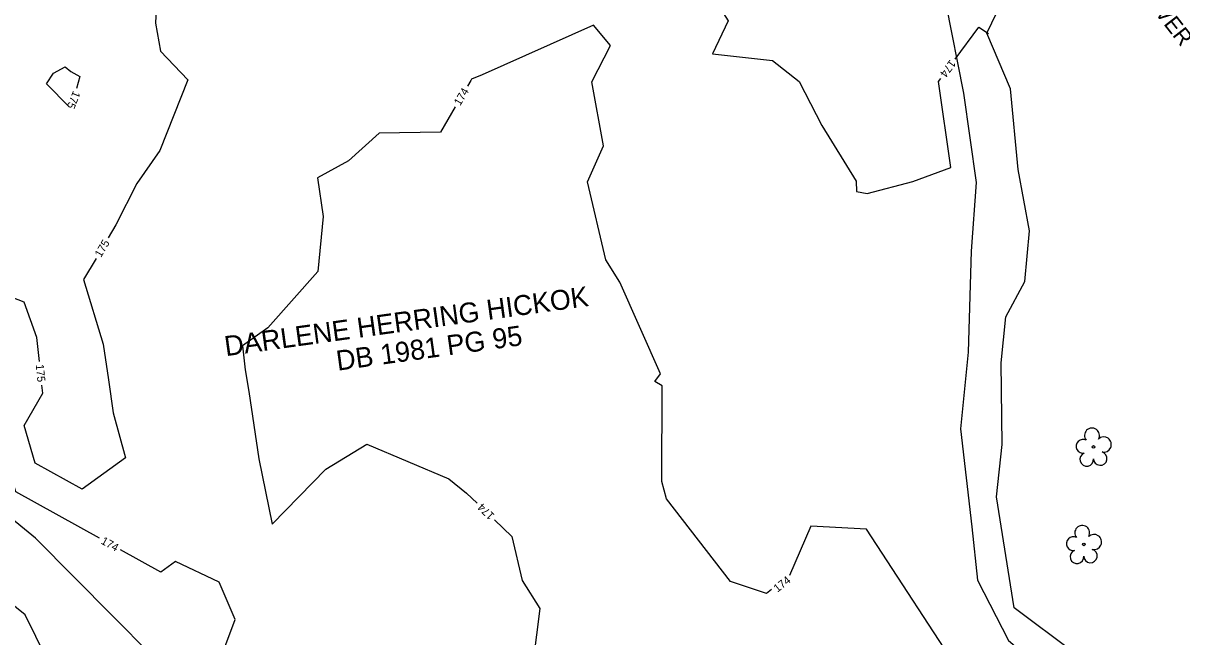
# Model space of a CAD drawing. Extents: x 2086416 to 2115205, y 575507 to 632762.
# Drawn here: x 2111776.5 to 2112066, y 581467.3 to 581620.8 of the extents above; entities that cross this region are included whole.
import ezdxf

# ---------------------------------------------------------------- set-up
doc = ezdxf.new("R2010")
doc.units = 0
for name, color, linetype in [('DTM Contours Major', 7, 'Continuous'), ('DTM Contours Major Text', 7, 'Continuous'), ('DTM Contours Minor', 7, 'Continuous'), ('DTM Contours Minor Text', 7, 'Continuous'), ('Exist Hydro Stream or Body of Water', 7, 'Continuous'), ('Exist Hydro Stream or Body of Water Text', 7, 'Continuous'), ('Exist Property Deed Book Text', 7, 'Continuous'), ('Exist Property Owner Text', 7, 'Continuous'), ('Exist Vegetation Tree CELL', 7, 'Continuous'), ('Exist Vegetation Woods Line', 7, 'Continuous')]:
    doc.layers.add(name, color=color, linetype=linetype)

# ---------------------------------------------------------------- blocks, each defined once
blk = doc.blocks.new('EXIST VEGETATION TREE')
at = {"layer": 'Exist Vegetation Tree CELL'}
blk.add_line((0, 0), (0, 0), dxfattribs=at)
blk.add_circle((0, 0), 0.00652, dxfattribs=at)
for centre, radius, start, end in [((-0.0077, 0.0575), 0.0371, 330.16508, 219.71335), ((-0.0521, 0.0031), 0.0345, 62.66361, 279.3457), ((0.051, 0.0118), 0.038, 257.1011, 134.19993), ((-0.0341, -0.0624), 0.0338, 111.56708, 6.23104), ((0.0335, -0.058), 0.034, 181.28216, 74.55999)]:
    blk.add_arc(centre, radius, start, end, dxfattribs=at)

msp = doc.modelspace()

# ---------------------------------------------------------------- linework, layer by layer
at = {"layer": 'DTM Contours Major'}
for points in [[(2111820.07, 581645.83), (2111817.92, 581646.44), (2111808.25, 581646.5), (2111811.2, 581641.49), (2111810.29, 581636.32), (2111809.51, 581620.82), (2111810.8, 581613.76), (2111817.65, 581606.62), (2111810.63, 581588.91), (2111804.83, 581580.65), (2111799.65, 581570.34), (2111797.73, 581567.1)], [(2111782.3, 581605.61), (2111784.01, 581608.29), (2111786.99, 581609.88), (2111788.36, 581608.71), (2111790.62, 581607.48), (2111789.82, 581604.42)], [(2111780.53, 581536.2), (2111779.91, 581542.21), (2111776.72, 581551.05), (2111767.61, 581554.53), (2111746.99, 581573.66), (2111745.59, 581575.02), (2111748.2, 581578.53), (2111769.31, 581602.49), (2111766.72, 581604.09), (2111762.55, 581607.47)], [(2111787.98, 581599.85), (2111782.3, 581605.61)], [(2111794.67, 581561.93), (2111791.54, 581556.65), (2111796.48, 581540.55), (2111797.78, 581531.62), (2111798.98, 581523.31), (2111802.05, 581512.09), (2111791.22, 581504.22), (2111779.44, 581510.73), (2111776.74, 581520.15), (2111781.34, 581528.23), (2111781.14, 581530.23)]]:
    msp.add_lwpolyline(points, dxfattribs=at)
at = {"layer": 'DTM Contours Minor'}
for points in [[(2112001.57, 581666.12), (2111965.52, 581661.61), (2111964.4, 581661.24), (2111963.9, 581661.19), (2111958.38, 581660.11), (2111945.74, 581643.25), (2111945.53, 581632.64), (2111952.64, 581621.35), (2111948.73, 581613.13), (2111963.74, 581611.46), (2111970.42, 581606.19), (2111976.09, 581595.16), (2111984.65, 581581.25), (2111984.7, 581578.65), (2111987.39, 581578.17), (2111998.82, 581581.21), (2112008.29, 581584.73), (2112005.23, 581606.22), (2112005.78, 581606.97)], [(2111963.5, 581479.12), (2111962.2, 581478.15), (2111953.21, 581481.17), (2111937.2, 581501.82), (2111936.07, 581506.16), (2111936.16, 581530.08), (2111934.34, 581531.17), (2111935.7, 581533.07), (2111925.59, 581555.99), (2111922.09, 581561.58), (2111917.53, 581581.13), (2111921.47, 581590.14), (2111918.62, 581606.14), (2111923.22, 581615.22), (2111918.98, 581620.26), (2111891.19, 581607.9), (2111888.52, 581606.78), (2111888.34, 581606.47), (2111887.5, 581605.04)], [(2112009.35, 581611.79), (2112015.27, 581619.77), (2112017.74, 581618.23)], [(2111884.45, 581599.87), (2111880.73, 581593.56), (2111865.45, 581593.25), (2111857.75, 581586.36), (2111850.01, 581582.13), (2111851.41, 581572.47), (2111850.12, 581558.71), (2111837.61, 581544.61), (2111831.26, 581540.08), (2111831.96, 581534.09), (2111832.86, 581528.7), (2111835.36, 581511.87), (2111838.72, 581495.5), (2111852.1, 581509.28), (2111862.32, 581515.47), (2111882.86, 581506.83), (2111887.27, 581503.23), (2111889.92, 581500.71)], [(2111795.57, 581491.95), (2111774.6, 581503.54), (2111772.79, 581509.85), (2111742.06, 581525.95)], [(2111894.26, 581496.57), (2111898.61, 581492.43), (2111901.19, 581481.43), (2111905.56, 581474.44), (2111901.59, 581442.83), (2111895.67, 581435.72), (2111904.81, 581432.38)], [(2111936.8, 581431.38), (2111937.22, 581432.68), (2111937.59, 581431.38), (2112017, 581428.25), (2112026.43, 581428.02), (2112017.76, 581430.28), (2112017.05, 581436.29), (2112012.18, 581454.89), (2112012.09, 581456.17), (2112011.8, 581456.57), (2111987.24, 581494.26), (2111973.35, 581495.02), (2111968.01, 581482.65)], [(2111808.47, 581449.49), (2111823.16, 581455.94), (2111824.76, 581459.12), (2111829.42, 581471.68), (2111825.46, 581480.96), (2111814.57, 581486.18), (2111810.87, 581483.49), (2111800.82, 581489.04)]]:
    msp.add_lwpolyline(points, dxfattribs=at)
at = {"layer": 'Exist Hydro Stream or Body of Water'}
for points in [[(2112026.79, 581556.19), (2112027.99, 581568.85), (2112025.16, 581584.18), (2112023.21, 581604.37), (2112017.27, 581618.27), (2112027.13, 581638.7)], [(2111785.01, 581456.38), (2111776.98, 581472.85), (2111753.02, 581492.1), (2111736.76, 581510.47), (2111717.38, 581521.12), (2111676.84, 581560.27), (2111646, 581586.7)], [(2112067.22, 581424.64), (2112074.1, 581427.73), (2112073.39, 581436.72), (2112064.5, 581445.16), (2112053.96, 581452.19), (2112024.09, 581474.58), (2112019.7, 581502.3), (2112021.09, 581515.42), (2112020.9, 581535.88), (2112022.05, 581547.38), (2112026.79, 581556.19)]]:
    msp.add_lwpolyline(points, dxfattribs=at)
at = {"layer": 'Exist Vegetation Woods Line'}
for points in [[(2112016.22, 581659.52), (2112010.15, 581640.89), (2112007.07, 581625.66), (2112011.47, 581603.31), (2112014.66, 581580.91), (2112013.34, 581563.73), (2112012.63, 581538.51), (2112010.71, 581519.35), (2112013.56, 581494.84), (2112014.97, 581481.49), (2112022.73, 581466.4), (2112037.51, 581453.75), (2112050.78, 581446.7), (2112062.82, 581439.28), (2112065.18, 581428.19)], [(2111779.57, 581491.97), (2111763.79, 581504.85), (2111745.34, 581525.06), (2111717.3, 581555.59), (2111690.35, 581575.95), (2111665.09, 581587.14), (2111644.35, 581594.34), (2111622.46, 581605.4), (2111614.18, 581617.92), (2111615.41, 581630.25), (2111644.69, 581636.02), (2111711.67, 581643.9), (2111763.23, 581655.57), (2111785.51, 581656)], [(2111823.9, 581373.12), (2111830.89, 581408.91), (2111827.79, 581443.34), (2111779.57, 581491.97)]]:
    msp.add_lwpolyline(points, dxfattribs=at)

# ---------------------------------------------------------------- block references
at = {"layer": 'Exist Vegetation Tree CELL', "xscale": 50, "yscale": 50}
for p in [(2112043.96, 581514.81), (2112041.52, 581490.44)]:
    msp.add_blockref('EXIST VEGETATION TREE', p, dxfattribs=at)

# ---------------------------------------------------------------- texts
at = {"layer": 'DTM Contours Major Text'}
for rotation, p in [(248.061, (2111788.99, 581604)), (59.348, (2111795.9, 581562.05)), (275.8302, (2111779.61, 581535.38))]:
    msp.add_text('175', height=2, rotation=rotation, dxfattribs=at).set_placement(p)
at = {"layer": 'DTM Contours Minor Text'}
for rotation, p in [(233.437, (2112008.12, 581611.8)), (59.4515, (2111885.68, 581599.99)), (136.3685, (2111894.42, 581497.8)), (331.0641, (2111795.72, 581490.72)), (38.149, (2111964.96, 581478.35))]:
    msp.add_text('174', height=2, rotation=rotation, dxfattribs=at).set_placement(p)
at = {"layer": 'Exist Hydro Stream or Body of Water Text'}
msp.add_text('BLACK RIVER', height=4, rotation=307.9408, dxfattribs=at).set_placement((2112044.15, 581642.61))
at = {"layer": 'Exist Property Deed Book Text'}
msp.add_text('DB 1981 PG 95', height=5, rotation=7.8831, dxfattribs=at).set_placement((2111855.06, 581533.86))
at = {"layer": 'Exist Property Owner Text'}
msp.add_text('DARLENE HERRING HICKOK', height=5, rotation=7.883, dxfattribs=at).set_placement((2111827.12, 581537.49))

doc.saveas('drawing.dxf')
